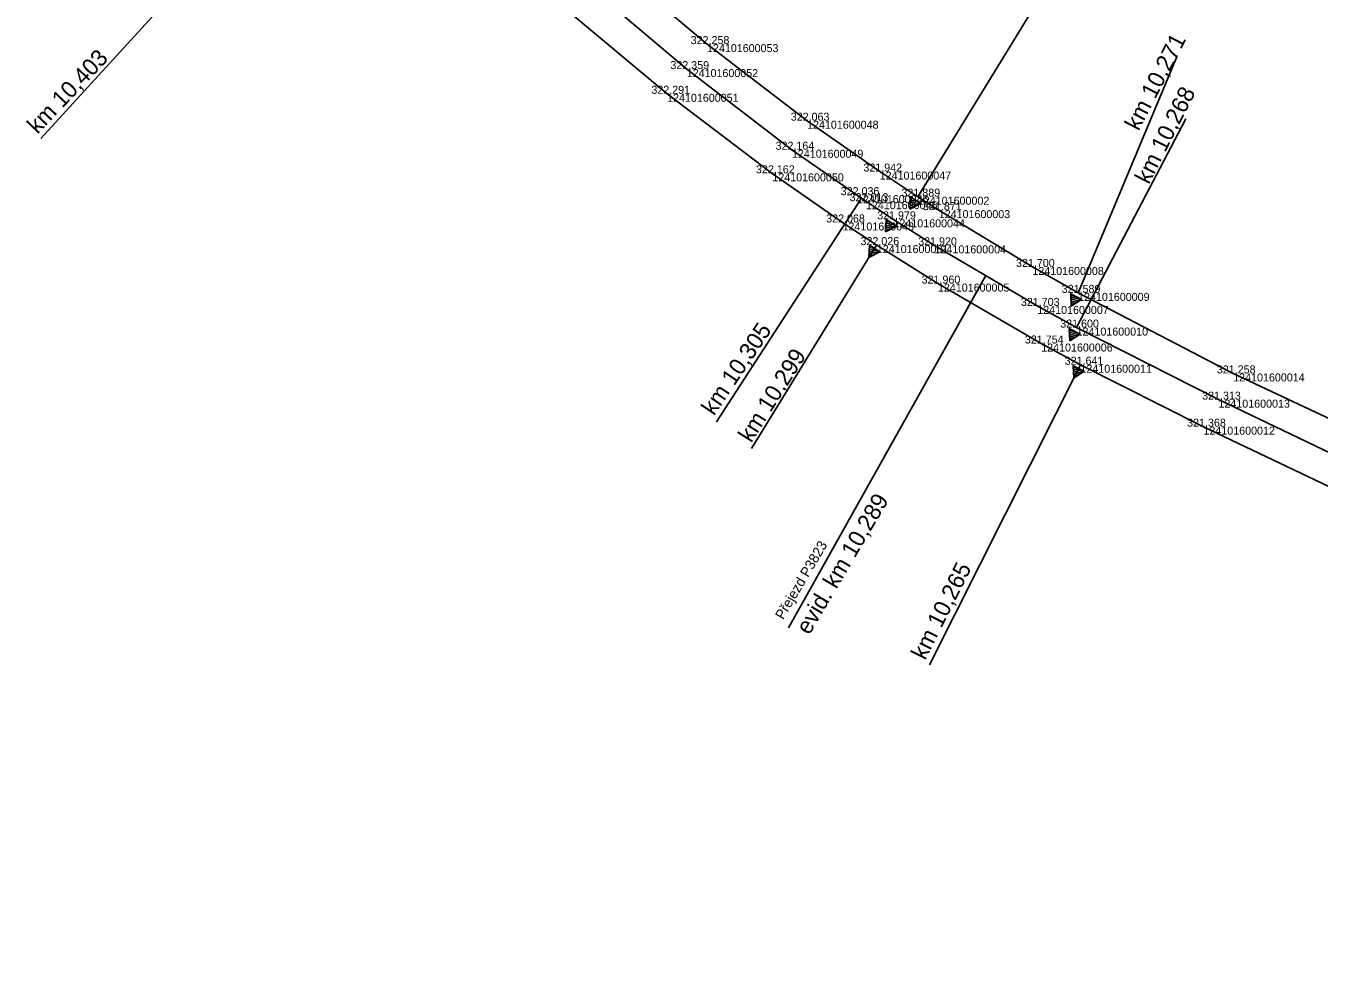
# Model space of a CAD drawing. Extents: x -616949 to -607976, y -1164436 to -1159224.
# Drawn here: x -616265.2 to -616071.3, y -1159889.9 to -1159749.3 of the extents above; entities that cross this region are included whole.
import ezdxf

# ---------------------------------------------------------------- set-up
doc = ezdxf.new("R2010")
doc.units = 0
for name, color, linetype in [('Vrstva 1', 7, 'Continuous'), ('Vrstva 3', 7, 'Continuous'), ('Vrstva 4', 7, 'Continuous'), ('Vrstva 60', 7, 'Continuous'), ('Vrstva 61', 7, 'Continuous')]:
    doc.layers.add(name, color=color, linetype=linetype)

msp = doc.modelspace()

# ---------------------------------------------------------------- linework, layer by layer
at = {"layer": 'Vrstva 1'}
for points in [[(-615908.84, -1159889.93), (-615910.27, -1159889.25), (-615923.84, -1159882.78), (-615939.55, -1159877.3), (-615950.02, -1159873.65), (-615958.35, -1159870.6), (-615972.88, -1159864.59), (-615984.54, -1159859.14), (-616001.22, -1159851.17), (-616023, -1159840.76), (-616044.09, -1159830.68), (-616066.72, -1159819.87), (-616088.67, -1159809.39), (-616107.11, -1159800.11), (-616112.99, -1159796.93), (-616128.47, -1159787.95), (-616137.63, -1159782.18), (-616142.77, -1159778.79), (-616153.3, -1159771.43), (-616169.07, -1159759.51), (-616184.52, -1159746.63), (-616200.28, -1159732.04), (-616217.13, -1159716.1), (-616218.05, -1159715.21)], [(-615938.86, -1159875.61), (-615940.27, -1159874.93), (-615953.84, -1159868.46), (-615968.03, -1159859.68), (-615983.58, -1159849.96), (-615996.64, -1159842.51), (-616003.45, -1159838.94), (-616018.15, -1159831.94), (-616039.7, -1159822.03), (-616063.66, -1159811.08), (-616084.21, -1159801.41), (-616107.46, -1159789.34), (-616114.32, -1159785.46), (-616128.35, -1159776.94), (-616131.48, -1159774.93), (-616137.2, -1159771.16), (-616148.09, -1159763.54), (-616163.09, -1159752.06), (-616177.88, -1159739.63), (-616193.93, -1159724.96), (-616196.14, -1159722.89)], [(-616064.75, -1159815.71), (-616086.42, -1159805.34), (-616107.69, -1159794.54), (-616113.58, -1159791.29), (-616128.98, -1159782.22), (-616135.14, -1159778.32), (-616139.26, -1159775.6), (-616140.6, -1159774.7), (-616150.36, -1159767.89), (-616166.13, -1159755.81), (-616181.17, -1159743.07)]]:
    msp.add_lwpolyline(points, dxfattribs=at)
at = {"layer": 'Vrstva 3'}
for p, q in [((-616217.13, -1159716.1), (-616262.93, -1159766.19)), ((-616131.48, -1159774.93), (-616105.43, -1159732.43)), ((-616107.46, -1159789.34), (-616092.64, -1159753.96)), ((-616107.69, -1159794.54), (-616091.33, -1159763.24)), ((-616139.26, -1159775.6), (-616140.6, -1159774.7)), ((-616139.93, -1159775.15), (-616161.65, -1159808.68)), ((-616131.95, -1159776.39), (-616132.69, -1159776.55)), ((-616131.11, -1159775.91), (-616132.67, -1159776.23)), ((-616131.47, -1159775.67), (-616132.66, -1159775.92)), ((-616131.83, -1159775.43), (-616132.64, -1159775.6)), ((-616132.2, -1159775.19), (-616132.61, -1159775.28)), ((-616135.48, -1159778.83), (-616136.28, -1159779.01)), ((-616135.85, -1159778.6), (-616136.26, -1159778.69)), ((-616135.58, -1159779.79), (-616136.31, -1159779.96)), ((-616134.74, -1159779.3), (-616136.3, -1159779.64)), ((-616135.11, -1159779.06), (-616136.29, -1159779.33)), ((-616137.64, -1159782.1), (-616156.43, -1159812.68)), ((-616137.97, -1159782.69), (-616138.77, -1159782.87)), ((-616138.34, -1159782.46), (-616138.75, -1159782.55)), ((-616138.07, -1159783.65), (-616138.8, -1159783.83)), ((-616137.23, -1159783.15), (-616138.79, -1159783.51)), ((-616137.6, -1159782.92), (-616138.78, -1159783.19)), ((-616108.15, -1159789.68), (-616108.55, -1159789.81)), ((-616107.76, -1159789.88), (-616108.54, -1159790.13)), ((-616107.38, -1159790.08), (-616108.53, -1159790.45)), ((-616106.99, -1159790.28), (-616108.51, -1159790.76)), ((-616107.78, -1159790.85), (-616108.49, -1159791.08)), ((-616108.36, -1159794.89), (-616108.77, -1159795.02)), ((-616107.97, -1159795.08), (-616108.75, -1159795.34)), ((-616107.59, -1159795.28), (-616108.74, -1159795.66)), ((-616107.2, -1159795.48), (-616108.72, -1159795.97)), ((-616107.98, -1159796.05), (-616108.7, -1159796.29)), ((-616107.11, -1159800.11), (-616129.72, -1159845.07)), ((-616107.79, -1159800.46), (-616108.2, -1159800.6)), ((-616107.4, -1159800.66), (-616108.18, -1159800.92)), ((-616107.02, -1159800.85), (-616108.16, -1159801.24)), ((-616106.63, -1159801.05), (-616108.14, -1159801.55)), ((-616107.41, -1159801.63), (-616108.12, -1159801.87))]:
    msp.add_line(p, q, dxfattribs=at)
for points in [[(-616132.7, -1159776.78), (-616131.05, -1159775.95), (-616132.6, -1159774.93)], [(-616136.33, -1159780.19), (-616134.69, -1159779.33), (-616136.25, -1159778.34)], [(-616138.81, -1159784.05), (-616137.17, -1159783.19), (-616138.74, -1159782.2)], [(-616108.49, -1159791.31), (-616106.93, -1159790.31), (-616108.57, -1159789.46)], [(-616108.69, -1159796.52), (-616107.14, -1159795.51), (-616108.79, -1159794.67)], [(-616108.11, -1159802.1), (-616106.56, -1159801.08), (-616108.22, -1159800.25)]]:
    msp.add_lwpolyline(points, close=True, dxfattribs=at)
at = {"layer": 'Vrstva 4'}
for p, q in [((-616114.32, -1159785.46), (-616128.35, -1159776.94)), ((-616113.58, -1159791.29), (-616128.98, -1159782.22)), ((-616121.28, -1159786.76), (-616150.88, -1159839.55)), ((-616112.99, -1159796.93), (-616128.47, -1159787.95))]:
    msp.add_line(p, q, dxfattribs=at)
at = {"layer": 'Vrstva 60'}
for p, q in [((-616163.09, -1159752.06), (-616163.09, -1159752.06)), ((-616166.13, -1159755.81), (-616166.13, -1159755.81)), ((-616169.07, -1159759.51), (-616169.07, -1159759.51)), ((-616148.09, -1159763.54), (-616148.09, -1159763.54)), ((-616150.36, -1159767.89), (-616150.36, -1159767.89)), ((-616137.2, -1159771.16), (-616137.2, -1159771.16)), ((-616153.3, -1159771.43), (-616153.3, -1159771.43)), ((-616140.6, -1159774.7), (-616140.6, -1159774.7)), ((-616131.48, -1159774.93), (-616131.48, -1159774.93)), ((-616139.26, -1159775.6), (-616139.26, -1159775.6)), ((-616128.35, -1159776.94), (-616128.35, -1159776.94)), ((-616142.77, -1159778.79), (-616142.77, -1159778.79)), ((-616135.14, -1159778.32), (-616135.14, -1159778.32)), ((-616137.63, -1159782.18), (-616137.63, -1159782.18)), ((-616128.98, -1159782.22), (-616128.98, -1159782.22)), ((-616114.32, -1159785.46), (-616114.32, -1159785.46)), ((-616128.47, -1159787.95), (-616128.47, -1159787.95)), ((-616107.46, -1159789.34), (-616107.46, -1159789.34)), ((-616113.58, -1159791.29), (-616113.58, -1159791.29)), ((-616107.69, -1159794.54), (-616107.69, -1159794.54)), ((-616112.99, -1159796.93), (-616112.99, -1159796.93)), ((-616107.11, -1159800.11), (-616107.11, -1159800.11)), ((-616084.21, -1159801.41), (-616084.21, -1159801.41)), ((-616086.42, -1159805.34), (-616086.42, -1159805.34)), ((-616088.67, -1159809.39), (-616088.67, -1159809.39))]:
    msp.add_line(p, q, dxfattribs=at)

# ---------------------------------------------------------------- texts
at = {"layer": 'Vrstva 3'}
for s, rotation, p in [('km 10,271', 62.5694, (-616098.4, -1159765.18)), ('km 10,403', 46.581, (-616263.44, -1159765.65)), ('km 10,268', 63.0858, (-616096.86, -1159773.19)), ('km 10,305', 56.0254, (-616162.04, -1159807.86)), ('km 10,299', 57.763, (-616156.46, -1159811.93)), ('km 10,265', 63.3108, (-616130.39, -1159844.5))]:
    msp.add_text(s, height=2.5, rotation=rotation, dxfattribs=at).set_placement(p)
at = {"layer": 'Vrstva 4'}
for s, height, p in [('evid. km 10,289', 2.5, (-616147.76, -1159840.71)), ('Přejezd P3823', 1.5, (-616151.67, -1159838.41))]:
    msp.add_text(s, height=height, rotation=59.486, dxfattribs=at).set_placement(p)
at = {"layer": 'Vrstva 60'}
for s, p in [('124101600053', (-616163.09, -1159753.26)), ('124101600052', (-616166.13, -1159757.01)), ('124101600051', (-616169.07, -1159760.71)), ('124101600048', (-616148.09, -1159764.74)), ('124101600049', (-616150.36, -1159769.09)), ('124101600047', (-616137.2, -1159772.36)), ('124101600050', (-616153.3, -1159772.63)), ('124101600046', (-616140.6, -1159775.9)), ('124101600002', (-616131.48, -1159776.13)), ('124101600045', (-616139.26, -1159776.8)), ('124101600003', (-616128.35, -1159778.14)), ('124101600043', (-616142.77, -1159779.99)), ('124101600044', (-616135.14, -1159779.52)), ('124101600001', (-616137.63, -1159783.38)), ('124101600004', (-616128.98, -1159783.42)), ('124101600008', (-616114.32, -1159786.66)), ('124101600005', (-616128.47, -1159789.15)), ('124101600009', (-616107.46, -1159790.54)), ('124101600007', (-616113.58, -1159792.49)), ('124101600010', (-616107.69, -1159795.74)), ('124101600006', (-616112.99, -1159798.13)), ('124101600011', (-616107.11, -1159801.31)), ('124101600014', (-616084.21, -1159802.61)), ('124101600013', (-616086.42, -1159806.54)), ('124101600012', (-616088.67, -1159810.59))]:
    msp.add_text(s, height=1.2, dxfattribs=at).set_placement(p)
at = {"layer": 'Vrstva 61'}
for s, p in [('322.258', (-616165.54, -1159752.06)), ('322.359', (-616168.58, -1159755.81)), ('322.291', (-616171.43, -1159759.51)), ('322.063', (-616150.54, -1159763.54)), ('322.164', (-616152.81, -1159767.89)), ('322.162', (-616155.75, -1159771.43)), ('321.942', (-616139.65, -1159771.16)), ('322.036', (-616143.05, -1159774.7)), ('322.013', (-616141.71, -1159775.6)), ('321.889', (-616133.94, -1159774.93)), ('321.871', (-616130.71, -1159776.94)), ('322.068', (-616145.23, -1159778.79)), ('321.979', (-616137.59, -1159778.32)), ('322.026', (-616140.08, -1159782.18)), ('321.920', (-616131.43, -1159782.22)), ('321.700', (-616116.77, -1159785.46)), ('321.960', (-616130.92, -1159787.95)), ('321.589', (-616109.92, -1159789.34)), ('321.703', (-616116.04, -1159791.29)), ('321.600', (-616110.14, -1159794.54)), ('321.754', (-616115.44, -1159796.93)), ('321.641', (-616109.47, -1159800.11)), ('321.258', (-616086.66, -1159801.41)), ('321.313', (-616088.87, -1159805.34)), ('321.368', (-616091.12, -1159809.39))]:
    msp.add_text(s, height=1.2, dxfattribs=at).set_placement(p)

doc.saveas('drawing.dxf')
